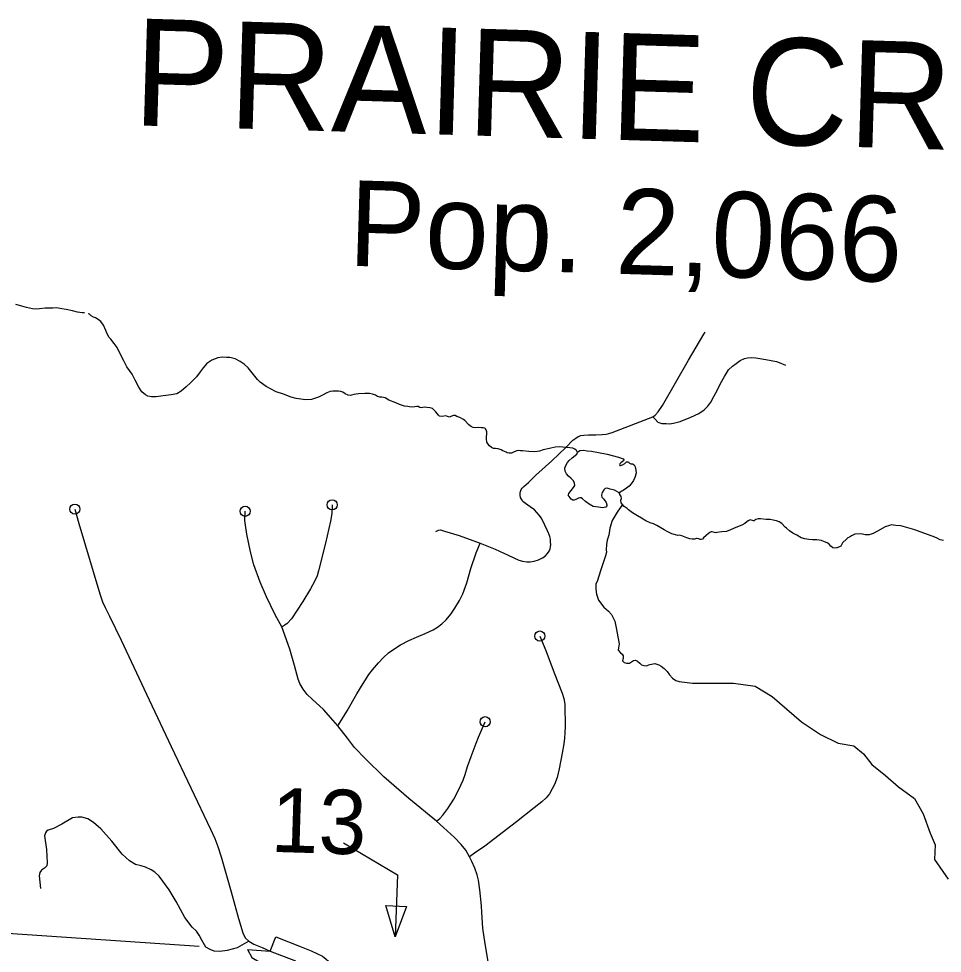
# Model space of a CAD drawing. Extents: x 653372 to 905732, y 627442 to 787275.
# Drawn here: x 700643 to 705201, y 731358 to 735972 of the extents above; entities that cross this region are included whole.
import ezdxf

# ---------------------------------------------------------------- set-up
doc = ezdxf.new("R2010")
doc.units = 0
for name, color, linetype in [('31', 7, 'Continuous'), ('32', 7, 'Continuous'), ('35', 7, 'Continuous'), ('56', 7, 'Continuous'), ('6', 7, 'Continuous')]:
    doc.layers.add(name, color=color, linetype=linetype)

msp = doc.modelspace()

# ---------------------------------------------------------------- linework, layer by layer
at = {"layer": '31'}
for points in [[(703772.5, 734006), (703784.1, 734015.1), (703799.1, 734031.4), (703819.2, 734062.9), (703948.2, 734285.5), (704024.7, 734413.9), (704030.3, 734423.5)], [(703772.5, 734006), (703784, 733994), (703797.1, 733980.2), (703817.1, 733973.4), (703837.9, 733972.8), (703855, 733972.3), (703874.7, 733974.8), (703908, 733983.6), (703960.6, 734004), (703999.1, 734021.9), (704025.4, 734040.7), (704043.7, 734059.1), (704058.4, 734078.9), (704073.9, 734106), (704091.7, 734140.3), (704105.7, 734171.5), (704125.9, 734204.9), (704146.5, 734238.5), (704164.8, 734257), (704183.3, 734270.3), (704203.9, 734283.8), (704224.4, 734293.6), (704239.8, 734297.4), (704259.5, 734299.3), (704280.2, 734297.4), (704330.2, 734288.6), (704383.2, 734279.6), (704395.1, 734274.4), (704427.7, 734261.8)], [(702701.1, 733440.2), (702714.2, 733447.3), (702724.5, 733447.7), (702744.8, 733441.6), (702816.5, 733420.3), (702920.5, 733382.4), (702994, 733353.6), (703057.5, 733322.6), (703110.7, 733298.5), (703129.7, 733293.2), (703150.4, 733290.8), (703167.2, 733291), (703187, 733293.1), (703207.4, 733300), (703228.1, 733309.7), (703240.3, 733318.8), (703252.9, 733331.1), (703260.7, 733343.8), (703265.9, 733354.9), (703267.5, 733365.1), (703268.2, 733376), (703267.9, 733388), (703266.6, 733403.1), (703263.6, 733415.1), (703258.9, 733428.6), (703252.8, 733444.1), (703239.7, 733471.8), (703222.3, 733506.5), (703212.1, 733520.4), (703199.9, 733534.8), (703188.4, 733547.1), (703167, 733562.7), (703143.6, 733578.8), (703130.9, 733589.1), (703123.7, 733599.5), (703119.6, 733608.5), (703117.8, 733619.5), (703117.8, 733629.1), (703119.4, 733637.9), (703122.8, 733647), (703127.8, 733654.4), (703135.9, 733663), (703158.3, 733682.1), (703194.9, 733718.2), (703274.1, 733788.5), (703343, 733855.1), (703377.8, 733890.5), (703391.5, 733901.7), (703404.3, 733908.5), (703417.4, 733913.6), (703432.2, 733915.9), (703455.1, 733916.9), (703490.2, 733917.2), (703523, 733918.6), (703541.7, 733920.8), (703554.6, 733923.8), (703571.5, 733929.1), (703772.5, 734006)], [(700919.3, 733550.9), (700940, 733478.9), (701043.4, 733132.7), (701056, 733093.3), (701069, 733065.3), (701091.3, 733022.1), (701148.7, 732904.1), (701274, 732636.9), (701395.9, 732379.2), (701590, 731971.6), (701610.6, 731924.7), (701624.9, 731886), (701641.2, 731834.3), (701690.5, 731662.1), (701727.8, 731530.5), (701748.4, 731459.1), (701760.7, 731435.2), (701778.1, 731418.4), (701802.8, 731403), (701843.8, 731386.4), (701884, 731369.1)], [(702963, 731297.5), (702944.7, 731404.1), (702934.1, 731481.6), (702928.3, 731560.3), (702926.5, 731591.7), (702919.3, 731671.8), (702911.9, 731719.8), (702905.2, 731746), (702894.5, 731778.4), (702878.5, 731811.6), (702867.2, 731834.6), (702848.7, 731867.3), (702826.4, 731896), (702794, 731929.1), (702738.8, 731979.2), (702705, 732010.9), (702568.4, 732122.2), (702444.7, 732229.7), (702353.8, 732317.8), (702300.2, 732374.7), (702264.8, 732420.8), (702217.3, 732480.6), (702195, 732507.6), (702146.8, 732561.6), (702090.4, 732613.1), (702066.5, 732635), (702046.1, 732662.2), (702029.9, 732689.3), (702021.6, 732710.8), (702003.9, 732778.9), (701980.4, 732860.1), (701941.2, 732969.5), (701909, 733028.9), (701865.3, 733118.3), (701834, 733190.2), (701802.5, 733275.8), (701786, 733340.5), (701768.8, 733426.3), (701761.2, 733470.9), (701759.2, 733494.2), (701760.6, 733539.9)], [(702190, 733572.1), (702187.3, 733528.5), (702181.5, 733491.8), (702156.4, 733383.3), (702122.2, 733245.4), (702115.3, 733221.7), (702104.4, 733197.4), (702083.4, 733157.1), (702044.6, 733094.1), (701988.9, 733009.7), (701967.7, 732985.8), (701956.5, 732978.6), (701941.2, 732969.5)], [(702217.3, 732480.6), (702237.4, 732512.8), (702263.9, 732555), (702312.1, 732638.2), (702342.4, 732690.5), (702370.3, 732734.8), (702388.7, 732758.1), (702417.7, 732791.4), (702443.1, 732818.6), (702468.4, 732841.1), (702489.8, 732856.5), (702527.4, 732880.6), (702567.6, 732901.9), (702605.7, 732918.5), (702649.2, 732937), (702688, 732955.6), (702710.2, 732967.9), (702731.2, 732983.7), (702752.9, 733003.5), (702775.6, 733032.9), (702795.6, 733061.6), (702817.9, 733099.9), (702833.8, 733132.4), (702854.5, 733186.4), (702874.4, 733256.8), (702900.6, 733334.5), (702912.4, 733363.5), (702920.5, 733382.4)], [(703214.7, 732924.1), (703243.5, 732853.3), (703284.6, 732742), (703324.7, 732642.2), (703332.3, 732616), (703337.3, 732588.7), (703338.8, 732555.6), (703339.4, 732504.9), (703339.4, 732478.3), (703338.4, 732445.7), (703336.4, 732420.2), (703333.1, 732392.2), (703324.6, 732346.8), (703310.5, 732268.5), (703299.6, 732226.5), (703286.4, 732191.3), (703276.2, 732170.3), (703261.6, 732145.6), (703246, 732125.2), (703224, 732105.3), (703187.1, 732076.3), (703098.9, 732007.7), (702942.9, 731887.2), (702892.9, 731852.7), (702867.2, 731834.6)], [(702705, 732010.9), (702720.5, 732023.7), (702735.7, 732040), (702760.1, 732073.2), (702789.5, 732119.2), (702812.7, 732164.1), (702835.5, 732213.3), (702846.8, 732241.2), (702858.4, 732279.8), (702875.8, 732329.9), (702900, 732395.3), (702912.2, 732425.7), (702923.4, 732451.3), (702944.6, 732501.4)], [(701771.9, 731376.5), (701884, 731369.1), (701910.9, 731439.1)], [(701910.9, 731439.1), (702036.9, 731390.8), (702085.7, 731370.3), (702141.7, 731343.7), (702160.7, 731328.9), (702183.4, 731309.4), (702213.2, 731250.2), (702224, 731224.6), (702237.5, 731190.9), (702241.5, 731155.2), (702239.9, 731081.8), (702236.9, 731003.7)], [(701771.9, 731376.5), (701792.9, 731336.9), (701857.2, 731299.1), (701981, 731251.6), (702024.4, 731233.4), (702062.5, 731215.2), (702063.1, 731214.8), (702076.9, 731187.3), (702085.3, 731167.6), (702090.7, 731153.9), (702091.3, 731148.6), (702089.9, 731086.4), (702087, 731009.4)], [(701884, 731369.1), (702008.9, 731321.2)]]:
    msp.add_lwpolyline(points, dxfattribs=at)
for centre in [(702190, 733572.1), (700919.3, 733550.9), (701760.6, 733539.9), (703214.7, 732924.1), (702944.6, 732501.4)]:
    msp.add_circle(centre, 25, dxfattribs=at)
at = {"layer": '32'}
msp.add_lwpolyline([(701778.1, 731418.4), (701721, 731385.2), (701671.8, 731371.2), (701635.1, 731367.4), (701606.7, 731369.1), (701588.3, 731376.2), (701565.9, 731389), (701546.6, 731423.7), (701532.7, 731447.7), (701520.3, 731467.6), (701498.9, 731487), (701463, 731534.4), (701419, 731613.8), (701385.8, 731671.7), (701335.8, 731739), (701315.3, 731758.3), (701296.9, 731770.3), (701268.9, 731782.5), (701246.3, 731789.7), (701218.9, 731796.2), (701189.4, 731815), (701153.8, 731846.9), (701102.1, 731911.1), (701048.6, 731972.8), (701012.2, 732004), (700983.5, 732021.1), (700954.4, 732029.3), (700936.6, 732030.7), (700908.8, 732026.6), (700855.3, 731994.9), (700814.8, 731973.4), (700787.8, 731966), (700779.5, 731961.4), (700775.2, 731953.4), (700770.7, 731938.1), (700780.1, 731870.3), (700783.8, 731805.2), (700780.9, 731790.6), (700770, 731778.8), (700755.8, 731767.8), (700747.4, 731756.7), (700743.7, 731741.3), (700750.7, 731677.7)], dxfattribs=at)
at = {"layer": '35'}
for points in [[(700711.3, 734539.1), (700681.2, 734545.7), (700657.8, 734552.2), (700629.2, 734560)], [(700967.4, 734518.9), (700955.5, 734520.2), (700933.6, 734523.7), (700908.4, 734529.1), (700876.9, 734535.8), (700855, 734539.9), (700828.6, 734544.2), (700810.7, 734541.9), (700773.7, 734542.4), (700745.9, 734538.6), (700727.4, 734538), (700711.3, 734539.1)], [(701949, 734117.4), (701913.6, 734130), (701863.6, 734156.3), (701834.8, 734177.4), (701821.9, 734191), (701801.3, 734215.3), (701775.7, 734247.3), (701754.9, 734266.4), (701735.7, 734280.2), (701710.6, 734292), (701685.4, 734298.5), (701668.2, 734299.6), (701646.2, 734300.2), (701625.9, 734296.8), (701596.5, 734286.1), (701571.7, 734269.6), (701552.6, 734248.8), (701538.7, 734227.8), (701520.7, 734204.1), (701490.4, 734174.4), (701468.4, 734154.3), (701444.7, 734133.7), (701422.4, 734119.9), (701395.1, 734114.4), (701355.7, 734110.3), (701320.3, 734105.6), (701297.8, 734104.6), (701280.6, 734108.6), (701269.2, 734114.1), (701250.8, 734129.1), (701234.8, 734152.7), (701217.3, 734187.2), (701202.1, 734217.2), (701176.6, 734253.7), (701160.8, 734283.1), (701142.3, 734320.6), (701128.7, 734348.7), (701113.7, 734367.6), (701097.6, 734390), (701089.7, 734397.2), (701078.6, 734416.5), (701073.5, 734432.9), (701060.4, 734459.3), (701048.2, 734476.4), (701034.1, 734487.2), (701021.6, 734494.5), (701012.5, 734498.3), (701000, 734505.6), (700991.6, 734512.8), (700985.4, 734515)], [(702775.3, 734008.2), (702769.4, 734004.4), (702758.6, 734007.6), (702750.6, 734011.3), (702732.6, 734007.8), (702720, 734009.9), (702714.3, 734014.7), (702701.6, 734031.2), (702692, 734040.2), (702684.1, 734047.4), (702673.8, 734050), (702657.7, 734051.6), (702643.9, 734053.8), (702630.6, 734051.3), (702622.5, 734052.7), (702614.6, 734057.5), (702607.1, 734056.6), (702597.2, 734055.2), (702579.9, 734054.5), (702562.6, 734056.8), (702546, 734059), (702521.4, 734067.3), (702504.3, 734075.3), (702469.5, 734088.4), (702450.8, 734099.4), (702434.7, 734102.8), (702424.4, 734103.7), (702414.1, 734107.4), (702403.9, 734113.5), (702389, 734118.6), (702374.1, 734121.3), (702351.6, 734120.9), (702320.4, 734120.1), (702296.6, 734117.3), (702284.4, 734113.1), (702278, 734111.5), (702268.2, 734113), (702254.6, 734120.3), (702242.7, 734127.6), (702231.8, 734131.4), (702220.9, 734132.3), (702206.5, 734132.7), (702193.2, 734133.1), (702179.3, 734130.6), (702162.9, 734124.8), (702141.8, 734113.3), (702122.5, 734102.9), (702087.3, 734091.8), (702057.3, 734090.4), (702011.8, 734096.4), (701987.2, 734103.5), (701949, 734117.4)], [(703400.9, 733830.2), (703395.1, 733839.5), (703387.8, 733846.1), (703378.1, 733851.6), (703362.6, 733852.6), (703328.7, 733857.1), (703311.4, 733858.8), (703291.1, 733856.5), (703262, 733849.3), (703231.3, 733843.3), (703212.6, 733836.3), (703189.4, 733834.1), (703160, 733835), (703128.4, 733838.3), (703119.1, 733838.6), (703108.2, 733840), (703101.3, 733839.1), (703087.3, 733833.7), (703075.5, 733827.7), (703063.9, 733826.4), (703053, 733827.8), (703047.9, 733831.5), (703032.5, 733837.7), (703023.5, 733843.7), (703008.6, 733848.2), (702996, 733849.8), (702985.6, 733849.5), (702976.5, 733854.4), (702966.4, 733863.9), (702959.7, 733871.6), (702952.4, 733880.5), (702951.2, 733897.3), (702952.3, 733931.9), (702949.1, 733941.8), (702945.8, 733946.5), (702942.4, 733949.5), (702935, 733952.1), (702925.7, 733951.2), (702909.6, 733952.8), (702894.9, 733952.7), (702886.2, 733952.9), (702877.1, 733956.7), (702864.1, 733966.3), (702844.5, 733987.7), (702837.2, 733993.1), (702819, 734002.3), (702804.2, 734008.5), (702796.2, 734012.2), (702788.2, 734013.1), (702775.3, 734008.2)], [(703341.1, 733762.7), (703350.9, 733780.3), (703359.3, 733790.5), (703374.7, 733803.3), (703396.6, 733821.7), (703400.9, 733830.2), (703405.1, 733835.3), (703412.1, 733840.3), (703430, 733840.9), (703448.4, 733838), (703469.2, 733836.3), (703504.2, 733830.6), (703546.1, 733822.4), (703603.4, 733807.4), (703626.2, 733798.6), (703628.4, 733793.9), (703627, 733788.8), (703614.1, 733779.9), (703608.7, 733773.8), (703608.6, 733769.7), (703609, 733766.2), (703611.9, 733765.6), (703622.4, 733769.3), (703634.1, 733775.3), (703643.1, 733784.8), (703646, 733784.8), (703651.7, 733783.4), (703653.4, 733781.1), (703657.3, 733777.5), (703663.6, 733775), (703672.2, 733773.6), (703680.7, 733769.3), (703685.6, 733759.3), (703688.6, 733742.5), (703689.8, 733727.4), (703684, 733706.2), (703676.7, 733692.6), (703665.2, 733675.6), (703655.6, 733663.2), (703642, 733653.8), (703626.7, 733643.3), (703619.7, 733640), (703606.7, 733631.3)], [(703606.7, 733631.3), (703582.9, 733644), (703561.1, 733649.3), (703546.8, 733653.8), (703536.3, 733651.8), (703529.8, 733645.6), (703521.9, 733632.6), (703518.6, 733618.8), (703521.2, 733608.9), (703530.2, 733600), (703541.8, 733583.5), (703546, 733571.2), (703544.7, 733566.1), (703539.9, 733559.9), (703524.3, 733557.5), (703503.6, 733559.8), (703477.1, 733564.1), (703457.8, 733575), (703440.3, 733587.7), (703425.8, 733602), (703417.8, 733606.8), (703412.6, 733606.4), (703405, 733604.3), (703392.7, 733597.8), (703384.6, 733595.7), (703377.7, 733595.3), (703368.6, 733600.2), (703358.6, 733613.2), (703355.2, 733618), (703355.4, 733622), (703357.3, 733628.3), (703369.3, 733642.9), (703380.7, 733657.6), (703386.8, 733667.8), (703385.4, 733679.4), (703380.5, 733690.5), (703369.3, 733701.3), (703356.9, 733713.2), (703346.9, 733725.6), (703339.2, 733738), (703338.5, 733752.4), (703341.1, 733762.7)], [(703987.3, 733406.3), (703977.5, 733403.2), (703966.5, 733402.7), (703954.4, 733404.8), (703940.2, 733409.4), (703914.8, 733419), (703908.1, 733420.9), (703902.2, 733421.5), (703895.5, 733421.3), (703884.2, 733423.3), (703865.4, 733428.5), (703846.3, 733439.2), (703828.1, 733448.6), (703811.1, 733458.4), (703792.3, 733469.9), (703774.8, 733477.6), (703758.6, 733483.5), (703737.8, 733493.4), (703716.7, 733505.4), (703697.2, 733517), (703672.4, 733532.5), (703652.2, 733547.4), (703644.8, 733553.1), (703631.2, 733563.6), (703622.7, 733574), (703616.6, 733581.8), (703613.7, 733595.7), (703617.3, 733603.6), (703616.7, 733612.5), (703609.8, 733622.4), (703609.1, 733626.2), (703606.7, 733631.3)], [(703622.7, 733574), (703596.4, 733535.7), (703571.5, 733494.8), (703560.3, 733457.2), (703554.9, 733422.2), (703547, 733397.3), (703543.5, 733375.9), (703541.3, 733350.1), (703543.1, 733338.6), (703538.3, 733320.8), (703514.5, 733245.4), (703499.4, 733197.8), (703491.7, 733180.1), (703491.4, 733169.3), (703491.7, 733155.7), (703494.6, 733131.2), (703503.7, 733101.3), (703530.6, 733066.1), (703553, 733046.7), (703569, 733029.8), (703585.2, 732997.7), (703592.6, 732957.3), (703600.1, 732920.5), (703605.5, 732885.9), (703602.1, 732866.6), (703601.8, 732855.1), (703613.5, 732841.2), (703620.5, 732834.5), (703626, 732825.7), (703626.4, 732817.1), (703623.1, 732801.4), (703630.8, 732794), (703642.1, 732790.1), (703657.2, 732789.6), (703676.9, 732802.7), (703687.1, 732805.9), (703696.9, 732800.6), (703708.1, 732790.2), (703716.5, 732782.8), (703727.1, 732778.9), (703740, 732777.8), (703757.4, 732784.5), (703781.9, 732788), (703801.8, 732782.4), (703813.1, 732774.9), (703827.8, 732764.4), (703842.5, 732749.6), (703854.9, 732732.7), (703868.7, 732716.5), (703885.6, 732705.3), (703901.9, 732700.5), (703968.7, 732690.9)], [(704619.4, 733389.8), (704605.2, 733395.7), (704593.5, 733398.2), (704580.9, 733399.4), (704560.2, 733398.4), (704542.2, 733401), (704522.1, 733404.6), (704505, 733409.3), (704482.6, 733422.6), (704463.9, 733431.2), (704446.6, 733443.5), (704432.7, 733457), (704426.1, 733461.8), (704408.4, 733480.4), (704396, 733488), (704382.6, 733492.2), (704365.5, 733496.1), (704351.7, 733499), (704331.9, 733499.6), (704304.2, 733502.5), (704292, 733502.9), (704281.4, 733499.9), (704275.8, 733495.8), (704271.9, 733493.4), (704268.9, 733493.1), (704264.3, 733494), (704258.1, 733496.8), (704252.7, 733497.8), (704248.8, 733495.8), (704242, 733493), (704236.4, 733488.6), (704226.4, 733480), (704211, 733471.6), (704181.2, 733459.9), (704155.1, 733448), (704135.1, 733440.2), (704113.1, 733437.9), (704088.2, 733435.7), (704083.9, 733434.1), (704077.3, 733436), (704065.3, 733438.1), (704059.4, 733437.8), (704053.4, 733435.5), (704047, 733429.8), (704036.1, 733420), (704023.1, 733408.2), (704017.1, 733402.4), (704011.5, 733400.1), (704005.7, 733401.5), (703998.6, 733404.3), (703991.5, 733406.2), (703987.3, 733406.3)], [(705207, 733396.6), (705190.2, 733398.8), (705172, 733409.5), (705151.2, 733416.8), (705091.2, 733438.9), (705064.8, 733448.6), (705030.5, 733458.1), (704996.2, 733468.3), (704971.7, 733470.3), (704949, 733472.6), (704940.5, 733470.4), (704918.4, 733462.6), (704881.5, 733441.8), (704860.1, 733430.2), (704840.5, 733424.1), (704821, 733424.2), (704807.5, 733426.3), (704797, 733429.3), (704769.6, 733426.7), (704753.1, 733419.1), (704743.7, 733411.8), (704735.2, 733408.7), (704727.4, 733401.8), (704708.8, 733385), (704700.2, 733367.1), (704682.4, 733358.8), (704678.5, 733359), (704667.1, 733358.5), (704660.4, 733360.4), (704650.6, 733368.3), (704642, 733376.9), (704632.2, 733383.6), (704619.4, 733389.8)], [(703968.7, 732690.9), (704170.9, 732692), (704276.6, 732677.4), (704361.1, 732626.1), (704506.6, 732501.1), (704599.4, 732438.1), (704687, 732395.3), (704764.1, 732381.5), (704811.7, 732342.7), (704853.1, 732289.8), (704920.4, 732236.2), (704984.6, 732179.7), (705063.3, 732122.8), (705106.9, 732046.9), (705141.3, 731951.1), (705165.4, 731893), (705163.2, 731821.3), (705229.2, 731724.6)]]:
    msp.add_lwpolyline(points, dxfattribs=at)
at = {"layer": '56'}
for p, q in [((702500.4, 731438.7), (702455.3, 731593.5)), ((702455.3, 731593.5), (702557.2, 731589.6)), ((702557.2, 731589.6), (702500.4, 731438.7))]:
    msp.add_line(p, q, dxfattribs=at)
msp.add_lwpolyline([(702246.4, 731903.7), (702512.2, 731745), (702500.4, 731438.7)], dxfattribs=at)
at = {"layer": '6'}
msp.add_lwpolyline([(701533.8, 731392.3), (700488.9, 731461.7), (700565.3, 734146.8)], dxfattribs=at)

# ---------------------------------------------------------------- texts
at = {"layer": '56'}
msp.add_text('13', height=316.8, rotation=358.28, dxfattribs=at).set_placement((701883.7, 731859.2))
at = {"layer": '6'}
for s, height, p in [('PRAIRIE CREEK', 527.999, (701202.7, 735445.5)), ('Pop. 2,066', 422.4, (702266.7, 734752.3))]:
    msp.add_text(s, height=height, rotation=358.28, dxfattribs=at).set_placement(p)

doc.saveas('drawing.dxf')
